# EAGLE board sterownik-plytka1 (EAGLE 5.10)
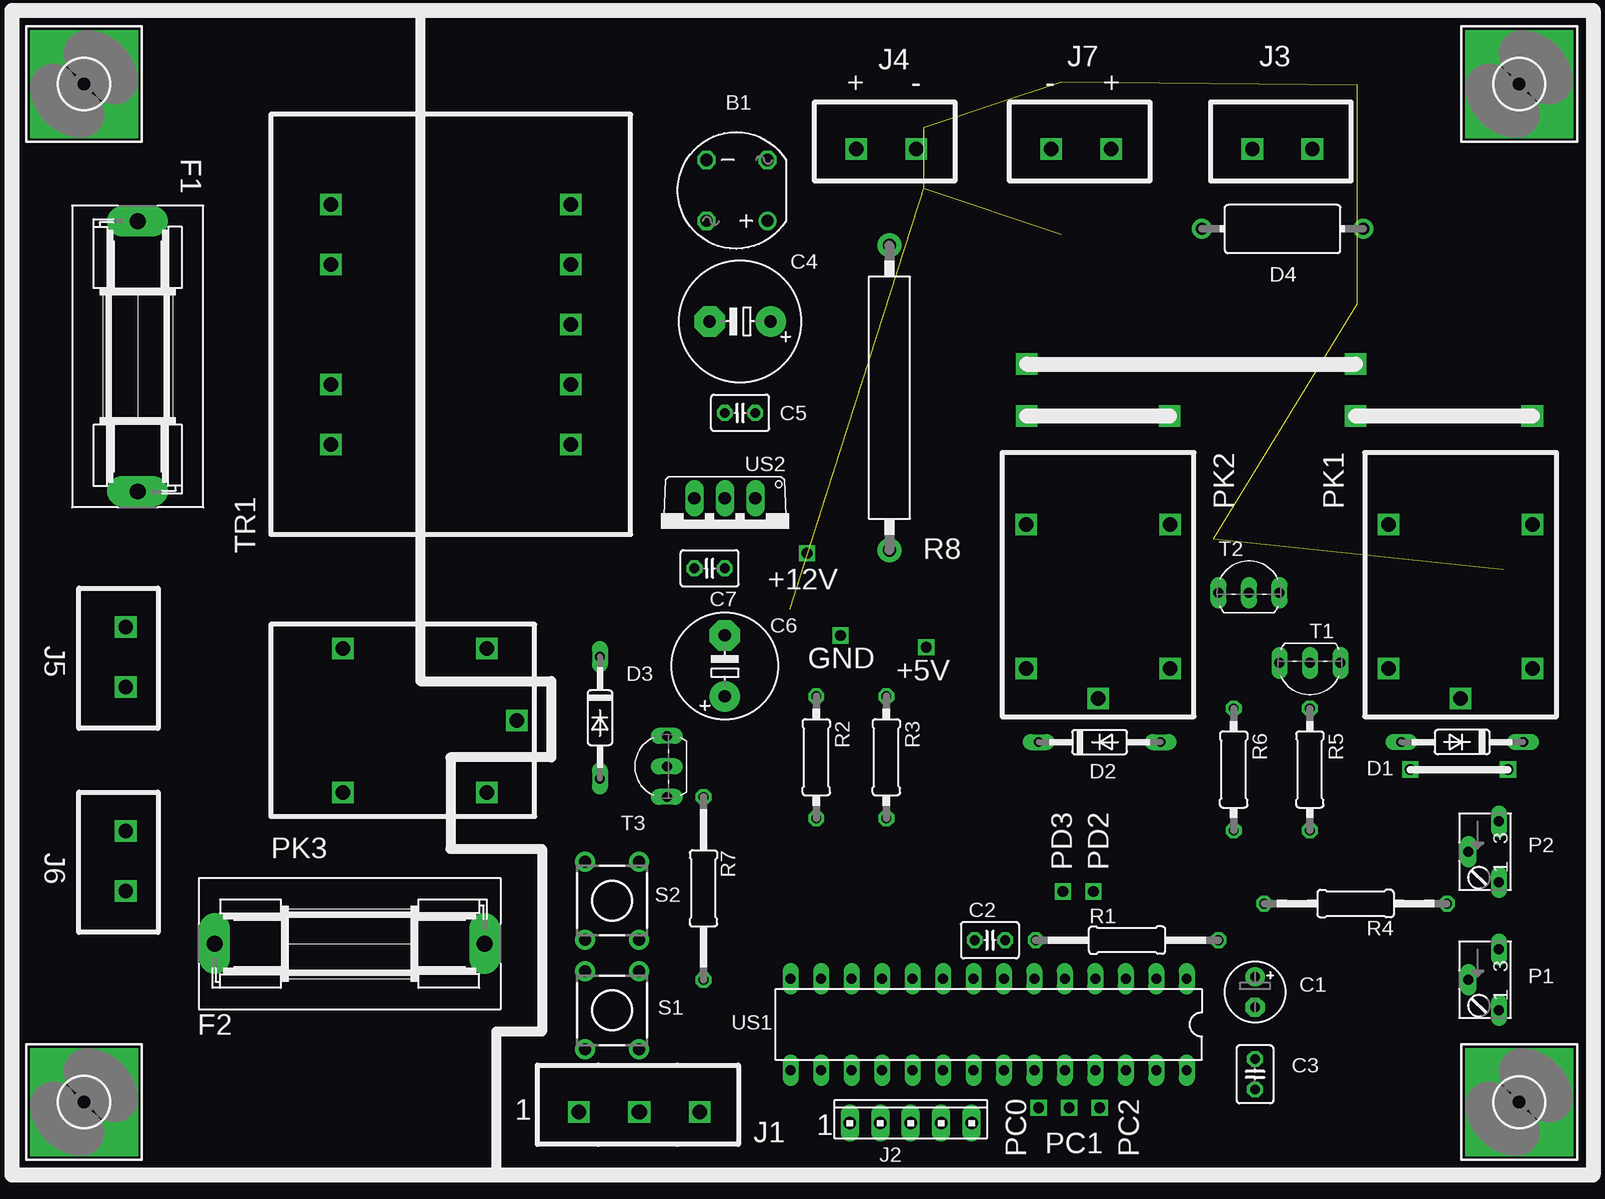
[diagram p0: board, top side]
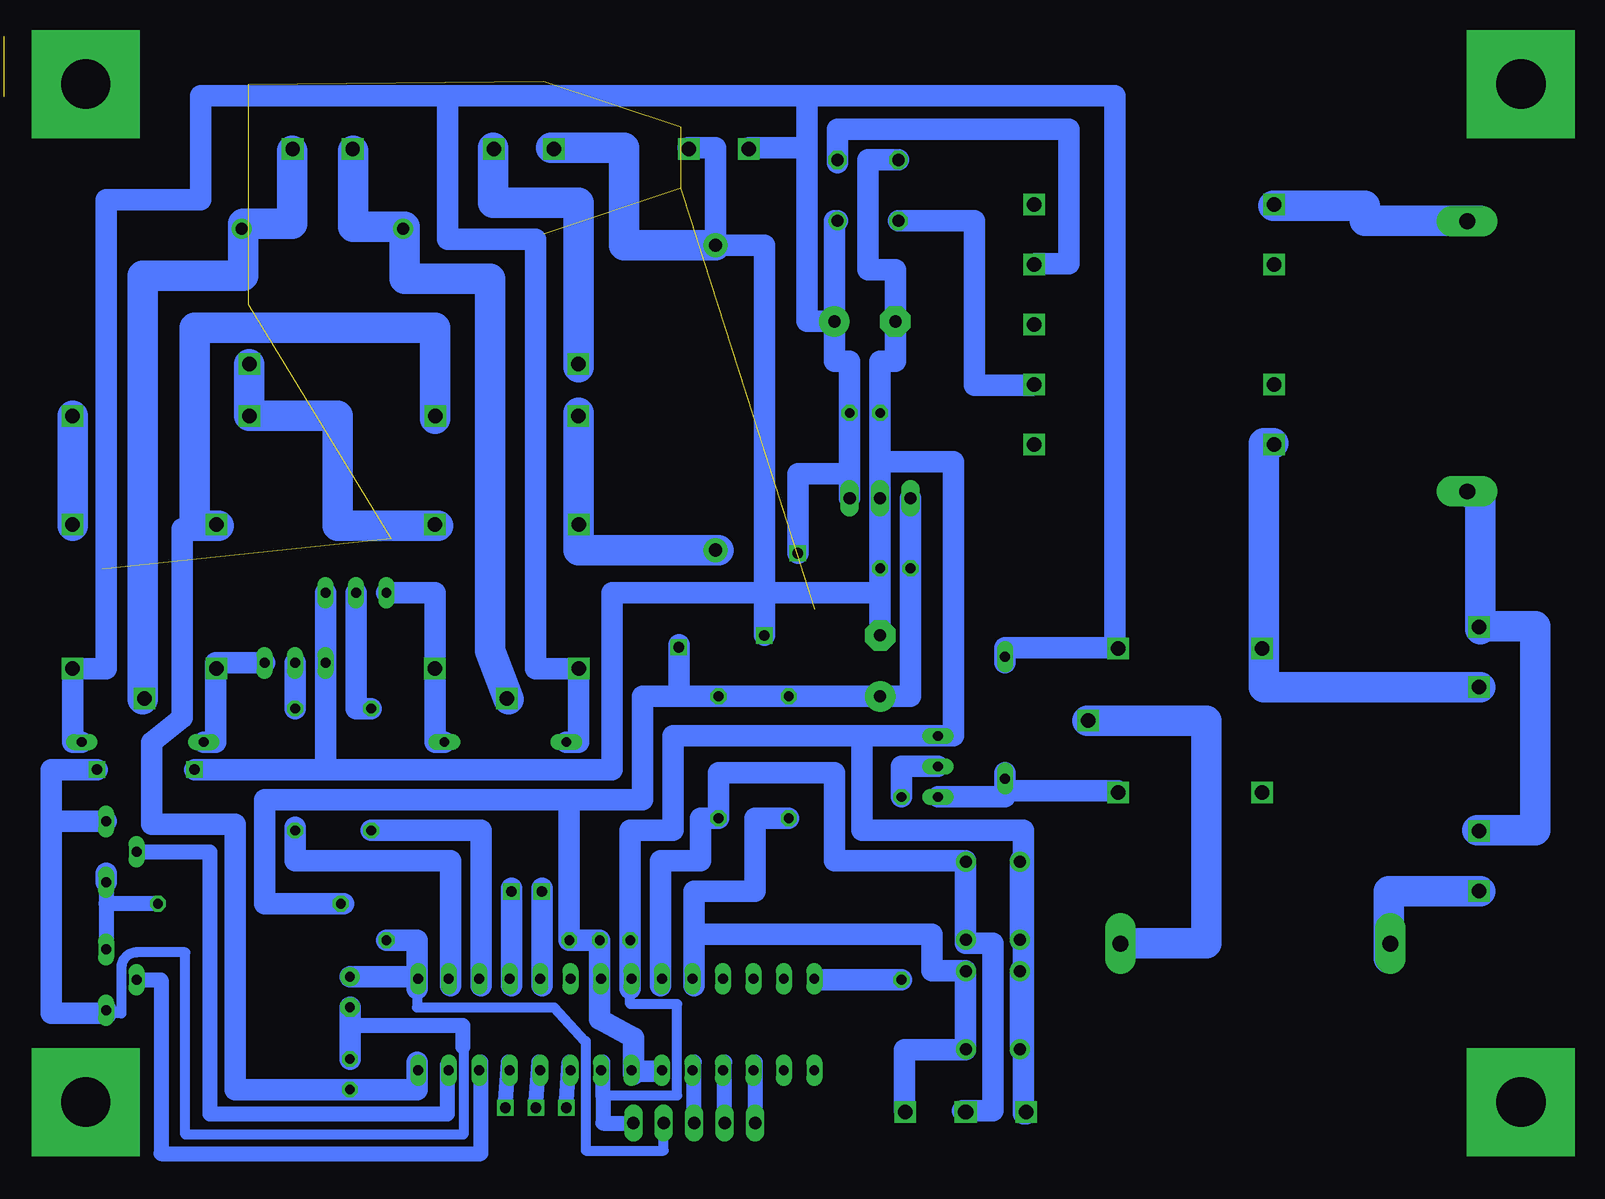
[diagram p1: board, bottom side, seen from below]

No outline drawn. Coordinates in mm, seen from the top.
Copper layers (1*16): Top 0.035mm / dielectric 1.5mm / Bottom 0.035mm
Design rules "default": minimum track width 10mil, minimum drill 24mil, track to track 8mil, track to pad 8mil, pad to pad 8mil, via to via 8mil, smd to smd 8mil, copper to edge 40mil, drill to drill 8mil, minimum pad ring 10mil, minimum via ring 8mil, stop-mask expansion 4mil, vias tented up to drill 0mil, thermal gap 10mil

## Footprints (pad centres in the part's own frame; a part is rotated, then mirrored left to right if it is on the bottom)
RB1A = drill 1.016 round: + -2.54,2.54 | drill 1.016 octagon: - 2.54,-2.54; AC1 2.54,2.54; AC2 -2.54,-2.54
E2,5-5 = drill 0.813 pad 1.6 round: + -1.27,0 | drill 0.813 pad 1.6 octagon: - 1.27,0
C025-030X050 = drill 0.813 octagon: 1 -1.27,0; 2 1.27,0
E5-10,5 = drill 1.016 pad 2.54 round: + -2.54,0 | drill 1.016 pad 2.54 octagon: - 2.54,0
E5-8,5 = drill 1.016 pad 2.54 round: + -2.54,0 | drill 1.016 pad 2.54 octagon: - 2.54,0
DO35-10 = drill 0.813 long: A 5.08,0; C -5.08,0
IRF-3 = drill 1 pad 1.676 round: 1 -6.705,0; 2 6.73,0
4,1-PAD-SQUARE = drill 4.1 pad 9 square: B4,1 0,0
SH22,5A = drill 1.321 pad 2.54 long: 1 -11.252,0; 2 11.252,0
10X05MTA = drill 1.016 long: 1 5.08,0; 2 2.54,0; 3 0,0; 4 -2.54,0; 5 -5.08,0
B64W = drill 0.813 long: A 2.54,0; E -2.54,0; S 0,-2.54
0207/15 = drill 0.813 octagon: 1 -7.62,0; 2 7.62,0
0207/10 = drill 0.813 octagon: 1 -5.08,0; 2 5.08,0
CA4080 = drill 1.1 pad 2 round: 1 -12.7,0; 2 12.7,0
TL1105 = drill 1 pad 1.676 round: 1 -2.25,3.25; 2 2.25,3.25; 3 -2.25,-3.25; 4 2.25,-3.25
TO92-BCE = drill 0.813 long: B -2.54,0; C 0,0; E 2.54,0
DIL28-3 = drill 0.813 long: 1 -16.51,-3.81; 2 -13.97,-3.81; 3 -11.43,-3.81; 4 -8.89,-3.81; 5 -6.35,-3.81; 6 -3.81,-3.81; 7 -1.27,-3.81; 8 1.27,-3.81; 9 3.81,-3.81; 10 6.35,-3.81; 11 8.89,-3.81; 12 11.43,-3.81; 13 13.97,-3.81; 14 16.51,-3.81; 15 16.51,3.81; 16 13.97,3.81; 17 11.43,3.81; 18 8.89,3.81; 19 6.35,3.81; 20 3.81,3.81; 21 1.27,3.81; 22 -1.27,3.81; 23 -3.81,3.81; 24 -6.35,3.81; 25 -8.89,3.81; 26 -11.43,3.81; 27 -13.97,3.81; 28 -16.51,3.81
TO220V = drill 1.016 long: 1 -2.54,-2.54; 2 0,-2.54; 3 2.54,-2.54

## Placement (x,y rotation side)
B1  [RB1A]  80.26,110.74 180 top
C1  [E2,5-5]  123.44,43.94 270 top
C2  [C025-030X050]  101.35,48.26 0 top
C3  [C025-030X050]  123.44,37.08 270 top
C4  [E5-10,5]  80.52,99.82 180 top
C5  [C025-030X050]  80.52,92.2 180 top
C6  [E5-8,5]  79.25,71.12 90 top
C7  [C025-030X050]  77.98,79.25 180 top
D1  [DO35-10]  140.72,64.77 180 top
D2  [DO35-10]  110.49,64.77 0 top
D3  [DO35-10]  68.83,66.8 270 top
D4  [IRF-3]  125.73,107.54 0 top
E$1  [4,1-PAD-SQUARE]  25.83,34.78 0 top
E$14  [4,1-PAD-SQUARE]  25.83,119.61 0 top
E$55  [4,1-PAD-SQUARE]  145.46,34.77 0 top
E$60  [4,1-PAD-SQUARE]  145.46,119.61 0 top
F1  [SH22,5A]  30.3,96.91 270 top
F2  [SH22,5A]  47.97,47.98 0 top
J2  [10X05MTA]  94.74,33.02 0 top
P1  [B64W]  143.76,44.96 270 top
P2  [B64W]  143.76,55.63 270 top
R1  [0207/15]  112.78,48.26 0 top
R2  [0207/10]  86.87,63.5 270 top
R3  [0207/10]  92.71,63.5 270 top
R4  [0207/15]  131.83,51.31 180 top
R5  [0207/10]  128.02,62.48 270 top
R6  [0207/10]  121.67,62.48 270 top
R7  [0207/15]  77.47,52.58 270 top
R8  [CA4080]  92.96,93.47 270 top
S1  [TL1105]  69.85,42.42 180 top
S2  [TL1105]  69.85,51.56 180 top
T1  [TO92-BCE]  128.02,71.37 180 top
T2  [TO92-BCE]  122.94,77.22 0 top
T3  [TO92-BCE]  74.42,62.74 90 top
US1  [DIL28-3]  101.24,41.24 180 top
US2  [TO220V]  79.25,82.55 180 top

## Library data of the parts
B1 = rectifier
C1-C7 D4 R1-R7 = rcl
D1-D3 = diode
E$1 E$14 E$55 E$60 = holes
F1 F2 = fuse
J2 = con-amp
P1 P2 = pot
R8 = resistor-power
S1 S2 = switch
T1-T3 US2 = transistor
US1 = 40xx

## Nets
S$96: C2.2 C6.+ R1.1 US2.3
S$98: T3.B
S$113: C1.- C3.1
S$122: R8.1
S$124: B1.+ C4.+ C5.1 D1.C D2.C US2.1
S$125: D2.A T2.B
S$126: D1.A T1.B
S$128: R7.1 T3.C
S$129: R6.1 T2.C
S$130: R5.1 T1.C
S$143: R3.2
S$147: R6.2
S$148: B1.- C2.1 J2.1 T2.E T3.E US2.2
S$152: R2.2
S$153: R1.2
S$154: C1.+
S$155: P2.A R4.1
S$159: P2.S
S$160: P1.S
S$162: C3.2
S$163: P1.A P2.E
S$164: R7.2

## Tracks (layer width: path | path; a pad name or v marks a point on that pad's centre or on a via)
S$1
  Bottom 2.54: 110.24,68.33 111.76,72.39 111.76,103.38 118.87,103.38 118.87,107.7 123.19,107.7 123.19,114.05
S$9  (2 unrouted)
S$12  (8 unrouted)
S$64  (via drill 1.2)
  other vias: 66.4,89.57
S$65  (via drill 1.2)
  other vias: 66.4,94.57
S$66  (via drill 1.2)
  other vias: 66.4,99.57
S$67  (via drill 1.2)
  other vias: 66.4,104.57
S$68  (via drill 1.2)
  other vias: 66.4,109.57
S$69  (via drill 1.2)
  other vias: 46.4,89.57
S$70  (via drill 1.2)
  other vias: 46.4,94.57
S$71  (via drill 1.2)
  other vias: 29.31,69.37
S$72  (via drill 1.2)
  other vias: 46.4,104.57
S$73  (via drill 1.2)
  other vias: 46.4,109.57
S$74  (via drill 1.2)
  other vias: 29.31,74.37
S$80  (via drill 1.2)
  other vias: 59.4,60.57
S$81  (via drill 1.2)
  other vias: 59.4,72.57
S$82  (via drill 1.2)
  other vias: 61.9,66.57
S$83  (via drill 1.2)
  other vias: 47.4,60.57
S$84  (via drill 1.2)
  other vias: 47.4,72.57
S$85  (via drill 1.2)
  other vias: 29.31,52.37
S$86  (via drill 1.2)
  other vias: 29.31,57.37
S$87
  Bottom 2.54: 46.48,109.47 38.86,109.47 38.86,108.2 29.21,108.2
S$88
  Bottom 1.778: 30.48,85.6 30.23,85.6
  Bottom 2.54: 30.23,85.6 29.21,85.6 29.21,74.42 | 29.21,74.42 29.21,74.17 | 29.21,74.42 24.64,74.42 24.64,57.4 29.46,57.4
S$89
  Bottom 2.54: 46.48,89.66 47.24,89.66 47.24,69.34 29.21,69.34
S$90
  Bottom 2.54: 61.98,66.55 52.07,66.55 52.07,48.01 59.18,48.01
S$91
  Bottom 2.54: 29.21,52.32 36.83,52.32 36.83,46.74
S$92
  Bottom 1.778: 66.29,104.65 63.5,104.65 63.5,115.82 82.8,115.82 82.8,113.03
S$93
  Bottom 1.778: 66.55,94.49 71.37,94.49 71.37,108.2 77.72,108.2
S$96
  Bottom 1.778: US2.3 76.71,68.58 C6.+ 99.06,68.58 99.06,59.94 105.16,59.94 | C2.2 R1.1 105.16,59.94 | 105.16,59.94 130.56,59.94 130.56,51.31 123.95,51.31
S$98
  Bottom 1.778: 59.44,60.71 68.83,60.71 | 68.83,60.71 68.83,62.23 | T3.B 68.83,60.2 68.83,60.71
S$99  (via drill 1.2)
  other vias: 104.36,70.9
S$100  (via drill 1.2)
  other vias: 116.36,70.9
S$101  (via drill 1.2)
  other vias: 110.36,68.4
S$102  (via drill 1.2)
  other vias: 104.36,82.9
S$103  (via drill 1.2)
  other vias: 116.36,82.9
S$104  (via drill 1.2)
  other vias: 134.59,70.9
S$105  (via drill 1.2)
  other vias: 146.59,70.9
S$106  (via drill 1.2)
  other vias: 140.59,68.4
S$107  (via drill 1.2)
  other vias: 134.59,82.9
S$108  (via drill 1.2)
  other vias: 146.59,82.9
S$109  (via drill 1.2)
  other vias: 123.22,114.2
S$110  (via drill 1.2)
  other vias: 128.22,114.2
S$111
  Bottom 2.54: 128.27,114.05 128.27,107.95 132.33,107.95 132.33,103.63 140.72,103.63 140.72,68.33
S$112  (via drill 1.2)
  Bottom 2.54: v146.56,91.95 146.56,82.8
S$113
  Bottom 1.778: C3.1 C1.-
S$114  (via drill 1.2)
  other vias: 116.33,91.95
S$115  (via drill 1.2)
  other vias: 104.39,91.95
S$116
  Bottom 2.54: 134.37,82.8 136.4,82.8 136.4,99.31 116.33,99.31 116.33,91.69
S$117
  Bottom 2.54: 92.71,80.77 104.39,80.77 104.39,92.2
S$118  (via drill 1.2)
  other vias: 106.45,114.2
S$119  (via drill 1.2)
  other vias: 111.45,114.2
S$120  (via drill 1.2)
  Bottom 2.54: 116.08,82.8 124.46,82.8 124.46,91.95 v131.83,91.95 v131.83,96.27
S$121  (via drill 1.2)
  other vias: 104.39,96.27
S$122
  Bottom 1.778: 100.58,106.17 100.84,106.17 | 95.25,114.3 92.96,114.3 R8.1
  Bottom 2.54: 106.68,114.3 100.58,114.3 100.58,106.17 R8.1
S$123
  Bottom 2.54: 111.51,114.3 111.51,109.73 104.39,109.73 104.39,96.01
S$124
  Bottom 1.778: US2.1 C5.1 81.79,96.52 83.06,96.52 C4.+ | D2.C 104.39,64.77 104.39,70.87 107.95,70.87 107.95,106.68 115.32,106.68 115.32,118.62 | B1.+ 83.06,108.2 C4.+ | C4.+ 85.34,99.82 85.34,114.3 | 85.34,114.3 90.17,114.3 | 85.34,118.62 85.34,114.3 | 85.34,118.62 115.32,118.62 | 85.34,118.62 59.69,118.62 59.69,72.64 | 68.83,71.37 68.83,72.64 59.69,72.64 | 59.69,72.64 59.44,72.64 | 115.32,118.62 135.89,118.62 135.89,109.98 143.76,109.98 143.76,70.87 146.56,70.87 146.56,64.77 D1.C
S$125
  Bottom 1.778: D2.A 116.33,64.77 116.33,77.22 T2.B
S$126
  Bottom 1.778: D1.A 134.62,64.77 134.62,71.37 T1.B
S$128
  Bottom 1.778: T3.C 77.47,62.74 R7.1
S$129
  Bottom 1.778: T2.C 122.94,67.56 R6.1
S$130
  Bottom 1.778: R5.1 T1.C
S$134  (via drill 1.2)
  other vias: 67.08,33.94
S$135  (via drill 1.2)
  other vias: 90.2,114.2
S$136  (via drill 1.2)
  other vias: 95.2,114.2
S$137  (via drill 1.2)
  other vias: 72.08,33.94
S$138
  Bottom 1.27: 89.66,38.1 89.66,32.26
S$139
  Bottom 1.27: 92.2,32.26 92.2,38.1
S$140  (via drill 1.2)
  other vias: 72.16,33.94
S$141  (via drill 1.2)
  other vias: 77.16,33.94
S$142
  Bottom 1.27: 94.74,32.26 94.74,38.1
S$143
  Bottom 1.778: 97.54,44.45 97.54,54.86 94.23,54.86 94.23,58.42 R3.2 92.71,62.23 83.06,62.23 83.06,54.86 72.14,54.86 72.14,48.26
S$144
  Bottom 1.778: 115.06,44.45 115.06,54.86 128.02,54.86 128.02,57.66
S$145
  Bottom 1.778: 97.79,37.34 99.57,37.34
S$146
  Bottom 1.778: 99.82,37.08 99.82,40.13 102.62,41.66 102.62,48.01
S$147
  Bottom 1.778: 112.52,44.45 112.52,57.4 R6.2
S$148  (via drill 0.9)
  Bottom 0.813: 100.08,44.96 100.08,44.2 100.08,42.93 96.16,42.93 96.16,35.31 102.36,35.31
  Bottom 1.27: J2.1 102.36,33.02 102.36,35.31 102.36,38.1
  Bottom 1.778: T2.E 125.48,62.48 | B1.- 80.26,113.28 80.26,104.14 77.98,104.14 77.98,96.52 79.25,96.52 79.25,88.14 | 79.25,88.14 US2.2 79.25,77.22 | 79.25,77.22 79.25,73.41 | 79.25,88.14 73.15,88.14 73.15,65.28 T3.E 96.52,65.28 96.52,57.4 100.08,57.4 C2.1 100.08,44.2 | 79.25,77.22 88.9,77.22 | 88.9,77.22 88.9,106.17 92.71,106.17 | 88.9,77.22 101.6,77.22 101.6,62.48 125.48,62.48 | 125.48,62.48 v136.4,62.48 | v88.9,73.66 88.9,77.22 | v86.11,80.52 86.11,87.12 82.55,87.12 | 96.01,69.34 96.01,72.9
  other vias: 109.98,52.32 96.04,72.68
S$149  (via drill 0.9)
  other vias: 107.44,52.32
S$150
  Bottom 1.778: 109.98,44.45 109.98,52.58
S$151
  Bottom 1.778: 107.44,44.45 107.44,52.58
S$152
  Bottom 1.778: R2.2 89.66,58.42 89.66,52.32 94.74,52.32 94.74,44.45
S$153
  Bottom 0.813: 117.86,44.7 117.86,42.67 106.43,42.67 103.89,39.88 103.78,39.88 103.78,30.73 97.28,30.73 97.28,32.26
  Bottom 1.778: R1.2 117.86,48.26 117.86,44.7 117.86,44.2
S$154
  Bottom 1.778: 117.86,45.21 C1.+
S$155
  Bottom 1.27: P2.A 143.76,51.31 | 143.76,51.31 143.76,46.99 | R4.1 143.76,51.31
  Bottom 1.778: P2.A 143.76,53.85
S$156  (via drill 0.9)
  Bottom 1.27: v110.49,34.29 110.24,38.1
S$157  (via drill 0.9)
  Bottom 1.27: v107.95,34.29 107.7,38.1
S$158  (via drill 0.9)
  Bottom 1.27: v105.41,34.29 105.16,38.1
S$159
  Bottom 1.27: P2.S 135.13,55.63 135.13,33.78 115.32,33.78 115.32,37.85
S$160
  Bottom 1.27: P1.S 139.19,44.96 139.19,30.48 112.52,30.48 112.52,38.1
S$161
  Bottom 1.778: 136.4,82.55 137.41,82.55 137.41,66.8 139.95,64.77 139.95,58.17
S$162
  Bottom 1.778: 139.95,57.91 132.99,57.91 132.99,35.81 C3.2 117.86,35.81 117.86,38.1
S$163  (via drill 0.9)
  Bottom 0.813: 113.97,39.17 113.97,32.05 137.16,32.05 137.16,47.24 141.22,47.24 arc-90 142.49,45.97 142.49,42.16 143.76,42.16
  Bottom 1.778: P2.E 148.34,58.17 | 148.34,58.17 148.34,42.16 143.76,42.16 P1.A | v144.53,62.48 148.34,62.48 148.34,58.17
S$164
  Bottom 1.778: R7.2 84.33,44.96
S$165
  Bottom 1.27: 114.05,39.37 114.05,41.15 123.7,41.15
S$166
  Bottom 1.778: 67.06,33.78 67.31,33.78 67.31,57.4 80.77,57.4 80.77,64.26
S$167
  Bottom 1.778: 94.49,48.77 74.93,48.77 74.93,45.72 72.14,45.72 72.14,39.12 77.22,39.12 77.22,34.04
S$168
  Bottom 1.778: 72.14,54.86 72.14,48.26
S$169
  Bottom 1.778: 67.56,48.26 67.56,54.86
S$170
  Bottom 1.778: 72.14,48.01 69.85,48.01 69.85,34.04 72.39,34.04
S$172
  Bottom 1.778: 67.56,39.12 67.56,45.72

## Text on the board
tNames: J4 | J7 | J3 | + | - | - | + | PK2 | PK1 | TR1 | +12V | J5 | GND | +5V | J6 | PK3 | PD3 | PD2 | PC0 | PC2 | 1 | 1 | J1 | PC1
